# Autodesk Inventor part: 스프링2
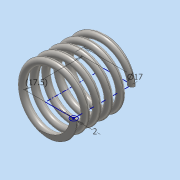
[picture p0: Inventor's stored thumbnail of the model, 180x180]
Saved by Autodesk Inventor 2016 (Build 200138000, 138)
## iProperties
Created: 2019-11
Part Number: 스프링2
Material: 스테인레스 스틸
Document SubType Name: Modeling
Designer: user
Density: 8 g/cm^3
Appearance: 반연마
Mass: 6.55763 g
Surface Area: 16.7049 cm^2
Volume: 0.819704 cm^3
Author: user
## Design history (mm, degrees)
sketch "스케치1"
  geometry: L1 (0, 0)-(8.5, 0); L2 (8.5, 0)-(8.5, 17.5); L3 (8.5, 17.5)-(0, 17.5); L4 (0, 17.5)-(0, 0); C1 r 1 at (8.5, 0)
  constraints: 8 end point, 2 parallel, 1 centre point, 1 coincident, 1 horizontal, 1 perpendicular
  dimensions: "d0" = 17 diameter of L2 L4; "d1" = 17.5 distance between parallel lines of L1 L3 (derived); "d2" = 2 diameter of C1
feature "코일1" sketch "스케치1" pitch "d3" = 10; turns "d5" = 5; dims "d4" = 17.5 (= d1), "d6" = 0, angle "d7" = 90 deg, angle "d8" = 90 deg, "d9" = 0, "d10" = 0
sketch "스케치2"
  geometry: L1 (-11.228, 0)-(11.228, 0); L2 (11.228, 0)-(11.228, 17.5); L3 (11.228, 17.5)-(-11.228, 17.5); L4 (-11.228, 17.5)-(-11.228, 0); 2 further points
  constraints: 8 end point, 2 parallel, 1 coincident, 1 horizontal, 1 midpoint, 1 perpendicular
  dimensions: "d11" = 17.5 distance between parallel lines of L1 L3 (= d1); "d12" = 22.45649 distance between parallel lines of L2 L4
extrude "돌출1" sketch "스케치2" stored distance "d13" = 42.25; taper "d14" = 0 deg
node "솔리드1"
